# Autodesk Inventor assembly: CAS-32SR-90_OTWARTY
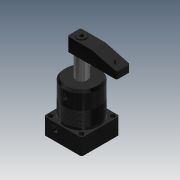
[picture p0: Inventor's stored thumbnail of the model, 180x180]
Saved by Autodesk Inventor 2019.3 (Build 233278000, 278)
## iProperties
Created: 2010-02
Part Number: CAS-32SR-90_OTWARTY
Material: Ogólny
Document SubType Name: Assembly
Designer: CADENGINEERING4
Sending System: PRO/ENGINEER BY PARAMETRIC TECHNOLOGY CORPORATION, 2007170
Preprocessor: PRO/ENGINEER BY PARAMETRIC TECHNOLOGY CORPORATION, 2007170
Title: CAS-32S_ASM
Author: Administrator
Revision Number: 2LAST_VERSION
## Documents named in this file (7)
- D:\Vault_2016\Projekty\STRONA\Pneumatic\Line ; Pipe connecct - type\cas-32s_asm\CAS-32SR-90_OTWARTY.iam
- D:\Vault_2016\Projekty\STRONA\Pneumatic\Line ; Pipe connecct - type\cas-32s_asm\CAS-32BT.ipt
- D:\Vault_2016\Projekty\STRONA\Pneumatic\Line ; Pipe connecct - type\cas-32s_asm\CAS-32SHSG.ipt
- D:\Vault_2016\Projekty\STRONA\Pneumatic\Line ; Pipe connecct - type\cas-32s_asm\CAS-32HG.ipt
- D:\Vault_2016\Projekty\STRONA\Pneumatic\Line ; Pipe connecct - type\cas-32s_asm\CAS-32SYB.ipt
- D:\Vault_2016\Projekty\STRONA\Pneumatic\Line ; Pipe connecct - type\cas-32s_asm\M8LC.ipt
- D:\Vault_2016\Projekty\STRONA\Pneumatic\Line ; Pipe connecct - type\cas-32s_asm\M4.ipt
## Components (9 placed, 9 different names)
1. CAS-32BT_0 — Kątowe:1
2. CAS-32SHSG_1 — Zestawiające:1, Zestawiające:2
3. CAS-32HG_2
4. CAS-32SYB_3 — Zestawiające:1, Zestawiające:2, Kątowe:1
5. M8LC_4
6. M4_5
7. M4_6
8. M4_7
9. M4_8
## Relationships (3: Mate 2, Angle 1)
- Zestawiające:1 [Mate]: CAS-32SHSG_1 ↔ CAS-32SYB_3
- Zestawiające:2 [Mate]: CAS-32SHSG_1 ↔ CAS-32SYB_3
- Kątowe:1 [Angle]: CAS-32BT_0 ↔ CAS-32SYB_3
